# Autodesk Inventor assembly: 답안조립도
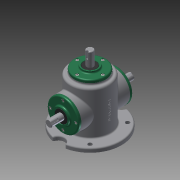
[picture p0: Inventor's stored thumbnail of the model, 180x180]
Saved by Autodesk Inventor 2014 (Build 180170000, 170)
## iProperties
Created: 2018-04
Part Number: 답안조립도
Document SubType Name: Assembly
Designer: kb542
Author: kb542
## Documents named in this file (16)
- C:\Users\kb542\Desktop\480407V1028\답안조립품.iam
- C:\Users\kb542\Desktop\480407V1028\본체.ipt
- C:\Users\kb542\Desktop\480407V1028\메인 베벨기어.ipt
- C:\Users\kb542\Desktop\480407V1028\메인 축.ipt
- 메인 축.ipt
- C:\Users\kb542\Desktop\480407V1028\베어링 6203.ipt
- C:\Users\kb542\Desktop\480407V1028\볼트 M4.ipt
- 볼트 M4.ipt
- C:\Users\kb542\Desktop\480407V1028\서브 베벨기어.ipt
- C:\Users\kb542\Desktop\480407V1028\서브 축.ipt
- 서브 축.ipt
- C:\Users\kb542\Desktop\480407V1028\오일 실.ipt
- 오일 실.ipt
- C:\Users\kb542\Desktop\480407V1028\커버.ipt
- C:\Users\kb542\Desktop\480407V1028\키 4x4.ipt
- C:\Users\kb542\Desktop\480407V1028\키 5x5.ipt
## Named parameters: d13_d4 = 0, d14_d5 = 0, d15_d6 = 0, d16_d7 = 0, d17_d8 = 0, d18_d9 = 0, d19_d10 = 0, d20_d11 = 0, d21_d12 = 0, d22_d0 = 0, d23_d1 = 0, d35_d13_d4 = 0, d36_d14_d5 = 0, d37_d15_d6 = 0, d38_d16_d7 = 0
